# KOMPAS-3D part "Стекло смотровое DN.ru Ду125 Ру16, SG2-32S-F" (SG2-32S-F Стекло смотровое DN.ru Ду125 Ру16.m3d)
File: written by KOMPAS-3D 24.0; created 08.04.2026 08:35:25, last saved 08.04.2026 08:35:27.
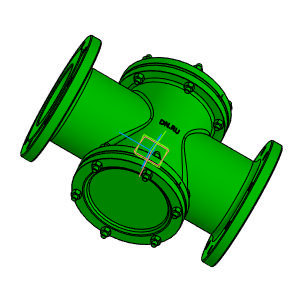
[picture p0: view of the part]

Document properties: Автор: Main; Полное имя файла: D:\DN.ru Аутсерс\Стекло смотровое DN.ru\SG2-32S-F Стекло смотровое DN.ru Ду125 Ру16\SG2-32S-F Стекло смотровое DN.ru Ду125 Ру16.m3d

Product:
- Body: Тело 1  | qty 1
    Масса: 38.267558
- Part/product: Стекло смотровое DN.ru Ду125 Ру16  | designation SG2-32S-F
    Масса: 36
    Раздел спецификации: Прочие изделия
    Примечание: D500-00112

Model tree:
1. Операция без истории:1

Expressions: SG2-32S-F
